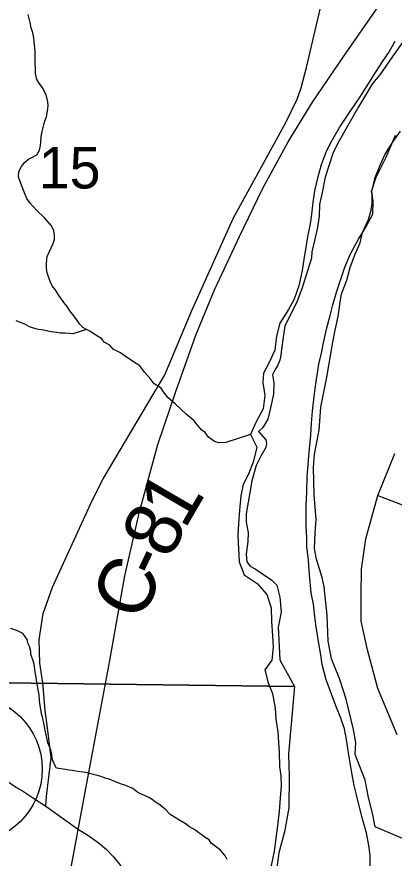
# Model space of a CAD drawing. Extents: x 0 to 34, y 0 to 22.
# Drawn here: x 5.367 to 5.747, y 17.947 to 18.793 of the extents above; entities that cross this region are included whole.
import ezdxf

# ---------------------------------------------------------------- set-up
doc = ezdxf.new("R2010")
doc.units = 0
for name, color, linetype in [('GM_X_City_Street', 7, 'Continuous'), ('GM_X_Corporation', 7, 'Continuous'), ('GM_X_County_Road', 7, 'Continuous'), ('GM_X_County_Road_Text', 7, 'Continuous'), ('GM_X_Major_River', 7, 'Continuous'), ('GM_X_Minor_River', 7, 'Continuous'), ('GM_X_Rail_Line', 7, 'Continuous'), ('GM_X_Section_Text', 7, 'Continuous'), ('GM_X_State_Route', 7, 'Continuous'), ('GM_X_Unincorporated', 7, 'Continuous')]:
    doc.layers.add(name, color=color, linetype=linetype)

msp = doc.modelspace()

# ---------------------------------------------------------------- linework, layer by layer
at = {"layer": 'GM_X_City_Street'}
msp.add_lwpolyline([(5.73022, 18.31154), (5.75148, 18.30377), (5.7629, 18.29884), (5.77638, 18.29418), (5.78883, 18.28976), (5.79946, 18.28691), (5.80309, 18.28619)], dxfattribs=at)
at = {"layer": 'GM_X_Corporation'}
for points in [[(5.75742, 18.77071), (5.74493, 18.75317), (5.73242, 18.73488), (5.72502, 18.72596), (5.71088, 18.70239), (5.69003, 18.6661), (5.68488, 18.65561), (5.67718, 18.63191), (5.67419, 18.61644), (5.67166, 18.60437), (5.67141, 18.59264), (5.66923, 18.57943), (5.66382, 18.55682), (5.66368, 18.55038), (5.65393, 18.51953), (5.64912, 18.50713), (5.64436, 18.49739), (5.63685, 18.4824), (5.63331, 18.45899), (5.63281, 18.45294), (5.63155, 18.44767), (5.62916, 18.44203), (5.6272, 18.43905), (5.62442, 18.43305), (5.62577, 18.42506), (5.62514, 18.41371), (5.62219, 18.39976), (5.61968, 18.38845), (5.61458, 18.38023), (5.61032, 18.37615), (5.61772, 18.36766), (5.61839, 18.36386), (5.61756, 18.36009), (5.61244, 18.35111), (5.60769, 18.34174), (5.60357, 18.3263), (5.59793, 18.29309), (5.59776, 18.28476), (5.59981, 18.27449), (5.59961, 18.2654), (5.59782, 18.25256), (5.59841, 18.24497), (5.60173, 18.24074), (5.60698, 18.23797), (5.62378, 18.22662), (5.62859, 18.2216), (5.63174, 18.20941), (5.63293, 18.19423), (5.62995, 18.17914), (5.63153, 18.14654), (5.64648, 18.1197), (5.16898, 18.12578)], [(6.08674, 17.82542), (5.72754, 17.97857), (5.72481, 17.99227), (5.72097, 18.00788), (5.71756, 18.02538), (5.70751, 18.05135), (5.70815, 18.06345), (5.70578, 18.07639), (5.69848, 18.10684), (5.69209, 18.12668), (5.68381, 18.14731), (5.68041, 18.16519), (5.67946, 18.19134), (5.67628, 18.21981), (5.67422, 18.22933), (5.66854, 18.24764), (5.6665, 18.25828), (5.66722, 18.27417), (5.66826, 18.28741), (5.66615, 18.31246), (5.6656, 18.33974), (5.66665, 18.35336), (5.67133, 18.37749), (5.67296, 18.40057), (5.67892, 18.43074), (5.68497, 18.46583), (5.68751, 18.4779), (5.69045, 18.49185), (5.69228, 18.50621), (5.69359, 18.51452), (5.69919, 18.5284), (5.70249, 18.54083), (5.70731, 18.55361), (5.71249, 18.56562), (5.71499, 18.57617), (5.72096, 18.5893), (5.7234, 18.59721), (5.7247, 18.60513), (5.72451, 18.61384), (5.72383, 18.61727), (5.72869, 18.63194), (5.73858, 18.6518), (5.74815, 18.67394)], [(5.16095, 17.13356), (5.16898, 18.12578), (5.64648, 18.1197), (5.64048, 18.05165), (5.64113, 18.02891), (5.64083, 17.99748), (5.63652, 17.97333), (5.63077, 17.95224), (5.62493, 17.90957)]]:
    msp.add_lwpolyline(points, dxfattribs=at)
at = {"layer": 'GM_X_County_Road'}
for points in [[(5.39632, 17.99927), (5.39677, 18.00895), (5.40165, 18.04791), (5.39781, 18.07811), (5.39541, 18.09545), (5.39302, 18.1234), (5.39025, 18.14299), (5.38939, 18.1664), (5.39349, 18.19297), (5.40305, 18.21954), (5.443, 18.30736), (5.45399, 18.32848), (5.51591, 18.43303), (5.54298, 18.49766), (5.58481, 18.59039), (5.63765, 18.68665), (5.64899, 18.71012), (5.65316, 18.72165), (5.65839, 18.74214), (5.67119, 18.79627), (5.6827, 18.84522), (5.69281, 18.86917), (5.88779, 19.11969)], [(5.74964, 18.07091), (5.73042, 18.11759), (5.71989, 18.15648), (5.71349, 18.18531), (5.71351, 18.21137), (5.71384, 18.23756), (5.7181, 18.26822), (5.73022, 18.31154), (5.7474, 18.35403)]]:
    msp.add_lwpolyline(points, dxfattribs=at)
at = {"layer": 'GM_X_Major_River'}
for points in [[(5.74745, 18.76828), (5.74155, 18.75813), (5.73491, 18.74838), (5.72747, 18.73712), (5.7208, 18.72622), (5.71296, 18.71345), (5.7028, 18.69882), (5.69263, 18.68382), (5.68359, 18.66803), (5.67844, 18.65749), (5.67324, 18.64428), (5.66996, 18.63218), (5.66664, 18.61818), (5.66489, 18.60643), (5.66351, 18.59467), (5.66218, 18.58481), (5.65964, 18.57194), (5.6579, 18.56095)], [(5.67902, 18.48032), (5.68231, 18.4928), (5.68518, 18.50339), (5.68885, 18.51624), (5.69208, 18.52606), (5.69694, 18.54117), (5.70291, 18.55474), (5.71079, 18.56941), (5.71824, 18.58143), (5.72533, 18.5946), (5.7256, 18.60752), (5.72428, 18.61743), (5.7276, 18.63143), (5.73278, 18.64387), (5.73756, 18.6548), (5.74578, 18.66756), (5.7532, 18.67806)], [(5.6579, 18.56095), (5.65619, 18.55148), (5.65402, 18.53784), (5.65067, 18.52269), (5.64623, 18.5091), (5.64032, 18.49857), (5.6317, 18.48505), (5.6284, 18.47181), (5.6266, 18.45778), (5.62104, 18.44534), (5.61513, 18.43481), (5.61456, 18.42532), (5.61657, 18.41236), (5.61478, 18.39871), (5.60768, 18.38516), (5.60212, 18.37311), (5.60869, 18.36043), (5.60497, 18.3453), (5.59978, 18.33248), (5.59465, 18.32269), (5.59252, 18.31133), (5.59109, 18.29692), (5.59006, 18.28363), (5.58943, 18.2711), (5.58993, 18.25816), (5.59079, 18.24484), (5.59584, 18.23182), (5.60894, 18.2232), (5.61857, 18.21198), (5.62285, 18.1986), (5.62334, 18.18528), (5.62418, 18.17044), (5.62508, 18.15902), (5.62368, 18.14612), (5.61666, 18.13637), (5.61981, 18.12339), (5.62414, 18.11266), (5.62687, 18.09778), (5.62779, 18.08674), (5.62981, 18.07415), (5.63034, 18.06312), (5.63091, 18.0536), (5.63137, 18.03915), (5.63269, 18.02962), (5.63287, 18.01973), (5.63186, 18.00721), (5.63084, 17.99431), (5.6294, 17.97951), (5.62762, 17.96662), (5.62585, 17.95411), (5.62249, 17.93783)], [(5.72258, 17.93624), (5.72248, 17.94993), (5.72117, 17.95984), (5.71877, 17.97243), (5.71523, 17.98505), (5.71206, 17.99689), (5.70892, 18.01064), (5.70646, 18.02019), (5.70372, 18.03469), (5.70068, 18.05299), (5.69868, 18.06634), (5.69662, 18.07702), (5.69304, 18.08774), (5.68871, 18.09847), (5.6844, 18.11034), (5.67828, 18.12642), (5.67442, 18.1417), (5.6731, 18.15161), (5.67072, 18.16496), (5.66836, 18.17945), (5.66705, 18.18974), (5.66541, 18.20232), (5.66336, 18.21377), (5.66146, 18.23205), (5.66062, 18.24651), (5.659, 18.26023), (5.65881, 18.26974), (5.65826, 18.28001), (5.65811, 18.29142), (5.65832, 18.30168), (5.65898, 18.31535), (5.65928, 18.33017), (5.66038, 18.34725), (5.66138, 18.35864), (5.66279, 18.3723), (5.66342, 18.38445), (5.66442, 18.39659), (5.66624, 18.41138), (5.66758, 18.42162), (5.67107, 18.4436), (5.67357, 18.45496), (5.67568, 18.46518), (5.67902, 18.48032)]]:
    msp.add_lwpolyline(points, dxfattribs=at)
at = {"layer": 'GM_X_Minor_River'}
for points in [[(5.60212, 18.37311), (5.57735, 18.36503), (5.57016, 18.36472), (5.56601, 18.36589), (5.55999, 18.3705), (5.55662, 18.37508), (5.55323, 18.37739), (5.54836, 18.38274), (5.54536, 18.38694), (5.5416, 18.39001), (5.53747, 18.39347), (5.5262, 18.40381), (5.51906, 18.41032), (5.51457, 18.41605), (5.51232, 18.41949), (5.50517, 18.4241), (5.50105, 18.42945), (5.49542, 18.43557), (5.49093, 18.44206), (5.4834, 18.44668), (5.47588, 18.45168), (5.47136, 18.45514), (5.46383, 18.459), (5.46045, 18.46283), (5.4548, 18.46591), (5.45256, 18.46935), (5.44541, 18.47359), (5.44127, 18.47666), (5.43712, 18.47859), (5.43335, 18.48053), (5.43035, 18.48397), (5.42699, 18.48855), (5.42436, 18.49236), (5.42024, 18.49733), (5.41763, 18.50191), (5.41425, 18.50573), (5.40901, 18.51337), (5.40565, 18.51871), (5.40265, 18.52253), (5.40079, 18.52634), (5.39856, 18.53243), (5.39708, 18.53661), (5.39674, 18.54155), (5.39677, 18.54496), (5.39717, 18.54875), (5.39758, 18.55216), (5.40372, 18.56499), (5.40488, 18.56916), (5.40492, 18.57333), (5.40419, 18.57827), (5.40158, 18.58322), (5.39521, 18.59049), (5.38657, 18.59891), (5.38057, 18.60579), (5.3772, 18.61037), (5.3746, 18.61609), (5.37088, 18.6256), (5.36866, 18.63207), (5.36908, 18.63738), (5.37177, 18.64266), (5.3752, 18.6468), (5.37862, 18.64981), (5.38204, 18.65167), (5.38698, 18.65428), (5.38966, 18.65881), (5.39083, 18.66373), (5.39123, 18.66713), (5.39165, 18.67282), (5.39244, 18.67774), (5.39439, 18.68569), (5.39555, 18.68909), (5.39671, 18.69249), (5.39749, 18.69628), (5.39828, 18.70044), (5.39868, 18.70385), (5.39833, 18.70765), (5.39649, 18.71449), (5.39276, 18.72174), (5.38939, 18.72632), (5.38715, 18.73013), (5.38568, 18.73621), (5.38572, 18.74114), (5.38538, 18.74608), (5.38547, 18.75859), (5.38512, 18.76201), (5.38441, 18.76808), (5.38405, 18.77188), (5.38295, 18.77682), (5.38148, 18.78214), (5.38039, 18.78746), (5.37855, 18.79545)], [(5.43712, 18.47859), (5.42348, 18.47417), (5.4197, 18.47458), (5.41554, 18.475), (5.41063, 18.47505), (5.40685, 18.47546), (5.40156, 18.47627), (5.39816, 18.47706), (5.39401, 18.47786), (5.38872, 18.47866), (5.38381, 18.47985), (5.37966, 18.4814), (5.37514, 18.4841), (5.36647, 18.48721)], [(5.57881, 17.94558), (5.57695, 17.94901), (5.57208, 17.95512), (5.56267, 17.96204), (5.56043, 17.96547), (5.55667, 17.96778), (5.55253, 17.97085), (5.545, 17.97623), (5.54124, 17.97816), (5.53748, 17.98123), (5.53334, 17.98354), (5.52129, 17.99086), (5.51641, 17.99622), (5.51002, 18.00121), (5.50663, 18.00313), (5.50325, 18.00582), (5.49986, 18.00813), (5.48893, 18.01316), (5.48366, 18.017), (5.47575, 18.02049), (5.47122, 18.02167), (5.45991, 18.02632), (5.45576, 18.0275), (5.45199, 18.02905), (5.44557, 18.03063), (5.44293, 18.03141), (5.43651, 18.03299), (5.42593, 18.0346), (5.42253, 18.03501), (5.41951, 18.03542), (5.41611, 18.03621), (5.40705, 18.03743), (5.40406, 18.04315), (5.40258, 18.04733), (5.40224, 18.05189), (5.40113, 18.05607), (5.39816, 18.06292), (5.39743, 18.06634), (5.39597, 18.07394), (5.39451, 18.08116), (5.39267, 18.08914), (5.39194, 18.09218), (5.39122, 18.09674), (5.39013, 18.10244), (5.38977, 18.10585), (5.38943, 18.11117), (5.3887, 18.11459), (5.38689, 18.12598), (5.38654, 18.12864), (5.38544, 18.13434), (5.38473, 18.13965), (5.384, 18.14345), (5.38104, 18.1522), (5.38106, 18.15486), (5.37958, 18.1598), (5.37846, 18.16247), (5.37736, 18.16703), (5.37512, 18.17008), (5.37287, 18.17276), (5.36759, 18.17546), (5.3608, 18.1778)]]:
    msp.add_lwpolyline(points, dxfattribs=at)
at = {"layer": 'GM_X_Rail_Line'}
msp.add_lwpolyline([(5.2481, 17.25711), (5.27249, 17.31025), (5.2997, 17.37208), (5.31751, 17.42325), (5.33302, 17.47575), (5.35127, 17.55496), (5.36152, 17.60386), (5.37233, 17.66649), (5.38993, 17.76213), (5.41588, 17.90711), (5.43929, 18.03317), (5.46057, 18.14565), (5.47575, 18.23079), (5.49042, 18.29535), (5.50883, 18.36307), (5.52708, 18.41615), (5.54717, 18.47282), (5.5659, 18.51845), (5.59118, 18.57222), (5.6141, 18.62009), (5.64022, 18.66742), (5.6647, 18.70739), (5.69609, 18.75367), (5.73067, 18.8031)], dxfattribs=at)
at = {"layer": 'GM_X_State_Route'}
for points in [[(5.34012, 18.03432), (5.35706, 18.02458), (5.36659, 18.01816), (5.37263, 18.01465), (5.38275, 18.00784), (5.39632, 17.99927), (5.40545, 17.99258), (5.41272, 17.98744)], [(5.41272, 17.98744), (5.42809, 17.97659), (5.43945, 17.96937), (5.44898, 17.96273), (5.45726, 17.9556), (5.4642, 17.94828), (5.47017, 17.94077), (5.47711, 17.93046), (5.48365, 17.90927), (5.48693, 17.89483), (5.49213, 17.87422), (5.49608, 17.86391), (5.50118, 17.85477), (5.50869, 17.84446), (5.51524, 17.83791), (5.52593, 17.83021), (5.53749, 17.82395), (5.54943, 17.81903), (5.56291, 17.81314)]]:
    msp.add_lwpolyline(points, dxfattribs=at)
at = {"layer": 'GM_X_Unincorporated'}
msp.add_circle((5.31813, 18.03643), 0.0744, dxfattribs=at)

# ---------------------------------------------------------------- texts
at = {"layer": 'GM_X_County_Road_Text'}
for s, rotation, p in [('1', 59.7739, (5.53577, 18.2765)), ('8', 63.75145, (5.52079, 18.24603)), ('-', 64.95716, (5.51105, 18.22517)), ('C', 65.30473, (5.49159, 18.18286))]:
    msp.add_text(s, height=0.05682, rotation=rotation, dxfattribs=at).set_placement(p)
at = {"layer": 'GM_X_Section_Text'}
msp.add_text('15', height=0.041856, rotation=0.00001, dxfattribs=at).set_placement((5.38896, 18.62046))

doc.saveas('drawing.dxf')
